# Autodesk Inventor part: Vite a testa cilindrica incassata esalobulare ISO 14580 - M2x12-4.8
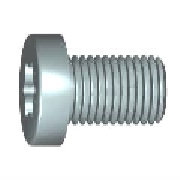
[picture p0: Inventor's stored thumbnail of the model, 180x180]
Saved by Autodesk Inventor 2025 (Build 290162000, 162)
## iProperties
Created: 2024-01
Part Number: Vite a testa cilindrica incassata esalobulare ISO 14580 - M2x12-4.8
Material: Acciaio
Description: ISO 14580 - Viti a testa cilindrica incassata esalobulare - Seconda edizione
Document SubType Name: Modeling
Standard: 14580
Designer: Ryzen5700u
Standards Organization: ISO
Language: it-IT
Size Designation: M2x12-4.8
Categories: <MemberInstance><Categories><Category DisplayName="Elementi di fissaggio" InternalName="e4da775c-781d-43d5-af7c-5136215cf5a6" Mnemonic="FSTN"><Category DisplayN
Density: 7.85 g/cm^3
Appearance: Lamiera
IsCustomPart: 0
Author: Ryzen5700u
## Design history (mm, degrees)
revolve "Revolution1" stored, may be unused: angle "d4" = 90 deg
thread "Thread1" dims "d6" = 12 (= b), "d7" = 0
sketch "Sketch2" dims "d21" = 1.75 (= A_)
  geometry: L1 (-0.53, -0.306)-(-0.875, 0); L2 (0, 0)-(-0.53, -0.306); L3 (0, 0)-(-0.53, 0.306); L4 (-2.85, 0)-(2.85, 0) reference; L5 (-0.875, 0)-(-0.53, 0.306); A1 r 0.613 centre (0, 0) between (-0.53, -0.306) and (-0.53, 0.306); 2 further points
  constraints: 8 end point, 2 coincident, 2 point on circle, 1 centre point, 1 horizontal alignment, 1 point on line, 2 other
  dimensions: "d19" = 60 deg angle of L3 L2; "d20" = 30 deg angle of L3 L4 (= 0.5 x d19); "d26" = 1.225 diameter of A1 (= 0.7 x d21)
extrude "Extrusion1" cut sketch "Sketch2" distance "d27" = 0.84 (= t); taper "d28" = 0 deg
pattern_circular "Circular Pattern1" dims angle "d30" = 360 deg
fillet "Fillet2" dims "d32" = 0.2 (= v)
fillet "Fillet3" dims "d33" = 0.2 (= v)
fillet "Fillet5" dims "d35" = 0.1 (= r)
chamfer "Chamfer2" distance "d36" = 0.2 (= v); stored, may be unused: second distance "d37" = 2, angle "d38" = 45 deg
body "Solid1"
sketch "Sketch1"
  geometry: L1 (0, 0)-(12, 0); L2 (12, 0)-(12, 1); L3 (12, 1)-(0, 1); L4 (0, 1)-(0, 0); L5 (0, 0)-(-1.55, 0); L6 (-1.55, 0)-(-1.55, 1.9); L7 (-1.55, 1.9)-(0, 2.036); L8 (0, 2.036)-(0, 0)
  constraints: 16 end point, 3 parallel, 2 horizontal, 2 perpendicular
  dimensions: "d0" = 2 diameter of L3 L1 (= d); "d3" = 12 distance of L2.end L3.end (= l_); "d46" = 85 deg angle of L8 L7; "d47" = 1.55 distance between parallel lines of L8 L6 (= k); "d49" = 3.8 diameter of L6.end L1 (= dk)
other parameters: "A_" = 1.75 [user parameter; used in 1 equation term], "d" = 2 [user parameter; used in 2 equation terms], "dk" = 3.8 [user parameter; used in 1 equation term], "k" = 1.55 [user parameter; used in 1 equation term], "l_" = 12 [user parameter; used in 2 equation terms], "lg" = 0 [user parameter; used in 1 equation term], "t" = 0.84 [user parameter; used in 1 equation term], "w" = 0.55 [user parameter], "v" = 0.2 [user parameter; used in 3 equation terms], "r" = 0.1 [user parameter; used in 1 equation term], "da" = 2.6 [user parameter], "ds_" = 2 (= d) [user parameter], "ls" = 0 [user parameter], "b" = 12 (= l_ - lg) [user parameter; used in 1 equation term], "d42" = 0, "d43" = 0, "d44" = 0, "p" = 0.4 [user parameter]
